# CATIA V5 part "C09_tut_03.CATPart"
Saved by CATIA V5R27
Part number: Part1
Bounding box of the stored display mesh (mm): x 0 to 224, y -87.726 to 88.949, z 0 to 67.082
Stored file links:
  E:\_Deepak\2017_Deepak\CATIA\Resources\Tutorial Files\Tutorials\c09_catia_v5_6r2016_tut\C09_tut_03.CATPart
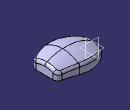
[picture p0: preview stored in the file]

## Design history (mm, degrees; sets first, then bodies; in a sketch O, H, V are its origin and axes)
Body1 (main body)
  Sketch1 on xy-plane, origin (0, 0, 0), H (1, 0, 0), V (0, 1, 0)
    arc A1 centre (95, -36.2404) radius 125 from (0, 45) to (139.6657, 80.5071) cw
    point P1 (95, -36.2404)
    point P2 (0, 45)
    arc A2 centre (289.027, 470.911) radius 418 from (139.6657, 80.5071) to (224, 58) ccw
    point P5 (224, 58)
    radius A1 = 125
    distance P2 H = 45
    distance P2 P5 H = 224
    radius A2 = 418
    distance P5 H = 58
    distance P1 V = 95
    coincidence: P2 V
    tangency: A2 A1
  Sketch2 on xy-plane, origin (0, 0, 0), H (1, 0, 0), V (0, 1, 0)
    axis line L1 (0, -58) -> (224, -58)
    point P1 (0, -58)
    point P2 (224, -58)
    arc A1 centre (112, 154.264) radius 240 from (0, -58) to (224, -58) ccw
    length L1 = 224
    radius A1 = 240
    distance H L1 = 58
    coincidence: P1 V
    horizontal: L1 H
  Sketch3 on zx-plane, origin (0, 0, 0), H (-1, 0, 0), V (0, 0, 1)
    arc A1 centre (-126.7082, -167.9142) radius 235 from (0, 30) to (-224, 46) ccw
    point P2 (0, 30)
    point P3 (-224, 46)
    axis line L1 (-224, 46) -> (-224, 0)
    point P4 (-224, 0)
    radius A1 = 235
    distance P2 H = 30
    length L1 = 46
    distance P2 P3 H = 224
    coincidence: P2 V, P4 H
    vertical: L1 V
  Sketch4 on yz-plane, origin (0, 0, 0), H (0, 1, 0), V (0, 0, 1)
    point P1 (45, 0)
    line L1 (45, 0) -> (45, 18.5632)
    point P3 (-58, 0)
    line L2 (-58, 0) -> (-58, 18.5632)
    arc A1 centre (-6.5, -89.8238) radius 120 from (-58, 18.5632) to (45, 18.5632) cw
    point P6 (0, 30)
    line L3 (45, 0) -> (-58, 0)
    reference projected point E1 (-58, 0) from Sketch2.P1
    reference projected point E2 (45, 0) from Sketch1.P2
    reference projected point E3 (0, 30) from Sketch3.P2
    construction line L4 (-58, 18.5632) -> (45, 18.5632)
    radius A1 = 120
    coincidence: P1 H, P3 H, A1 P6, P6 V, P3 E1, P1 E2, P6 E3
    vertical: L1 V, L2 V
    horizontal: L3 H, L4 H
  Plane1: type 3Points, Element1 Sketch2.P2, Element2 Sketch3.P3, Element3 Sketch1.P5
  Sketch5 on Plane1, origin (224, 0, 0), H (0, -1, 0), V (0, 0, 1)
    point P1 (-58, 0)
    line L1 (-58, 0) -> (58, 0)
    point P2 (58, 0)
    line L2 (58, 0) -> (58, 29.9794)
    arc A1 centre (0, -67) radius 113 from (58, 29.9794) to (-58, 29.9794) ccw
    point P5 (0, 46)
    line L3 (-58, 29.9794) -> (-58, 0)
    reference projected point E1 (-58, 0) from Sketch1.P5
    reference projected point E2 (58, 0) from Sketch2.P2
    reference projected point E3 (0, 46) from Sketch3.P3
    axis line L4 (58, 29.9794) -> (-58, 29.9794)
    radius A1 = 113
    coincidence: P1 H, A1 P5, P5 V, P1 E1, P2 E2, P5 E3
    horizontal: L1 H, L4 H
    vertical: L2 V, L3 V
  Loft1: solid, Sections (Sketch4; Sketch5), Guides (Sketch1; Sketch3; Sketch2)
  Fillet1: radius 25, on edge [face of Loft1 | face of Loft1] (x2)
  Fillet2: radius 15, on edge [face of Loft1 | face of Loft1]
  Shell1: ExtOffset 0, Face (face of Loft1; face of Loft1), IntOffset 3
